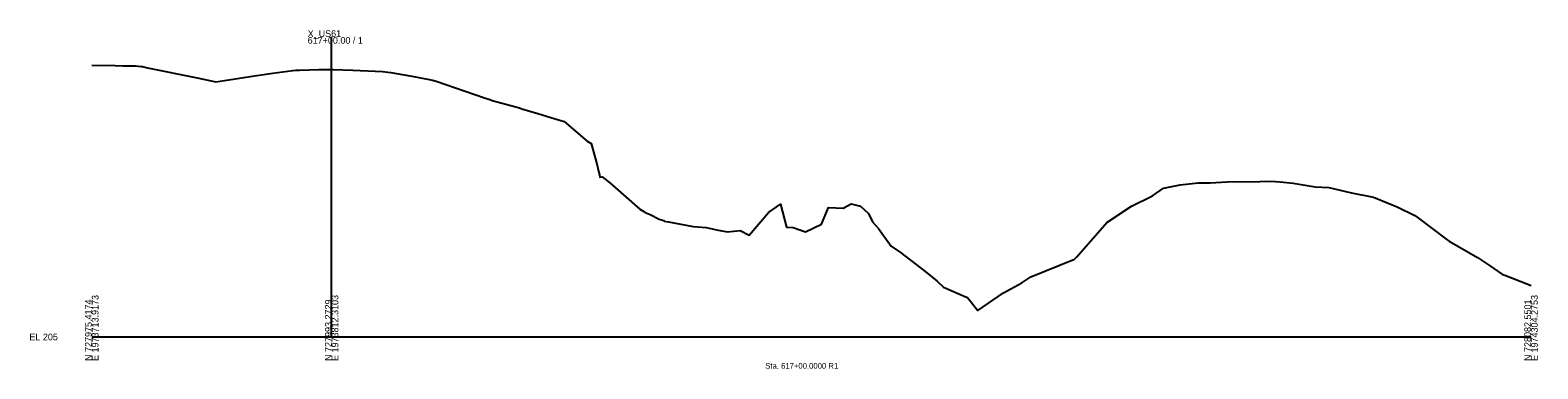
# Model space of a CAD drawing. Extents: x -26 to 1604, y -13 to 9623.
# Drawn here: x 974 to 1603, y 2487 to 2628 of the extents above; entities that cross this region are included whole.
import ezdxf

# ---------------------------------------------------------------- set-up
doc = ezdxf.new("R2010")
doc.units = 0
for name, color, linetype in [('Draft_XS_Grid', 7, 'Continuous'), ('Draft_XS_Text', 7, 'Continuous'), ('DTM_X_GROUND', 7, 'Continuous'), ('XS_CELL', 7, 'Continuous')]:
    doc.layers.add(name, color=color, linetype=linetype)

msp = doc.modelspace()

# ---------------------------------------------------------------- linework, layer by layer
at = {"layer": 'DTM_X_GROUND'}
msp.add_lwpolyline([(1000, 2613.3), (1009.7, 2613.09), (1012.95, 2613.02), (1018.24, 2612.91), (1020.77, 2612.73), (1020.83, 2612.73), (1021.09, 2612.66), (1023.27, 2612.11), (1043.99, 2607.92), (1051.71, 2606.3), (1055.34, 2606.87), (1067.82, 2608.83), (1075.44, 2609.96), (1077.62, 2610.25), (1083.78, 2611.07), (1085.11, 2611.15), (1086.6, 2611.24), (1094.61, 2611.39), (1100.62, 2611.51), (1108.76, 2611.15), (1121.14, 2610.61), (1123.39, 2610.38), (1124.73, 2610.25), (1134.91, 2608.37), (1142.04, 2607.04), (1143.53, 2606.57), (1163.71, 2599.61), (1165.91, 2598.94), (1166.88, 2598.47), (1176.16, 2596.01), (1178.26, 2595.5), (1179.32, 2595.03), (1185.89, 2593.09), (1193.15, 2590.84), (1196.89, 2589.73), (1206.47, 2581.64), (1208.13, 2580.62), (1210.55, 2572.2), (1211.2, 2569.14), (1211.67, 2567.57), (1211.81, 2566.52), (1212.78, 2566.67), (1215.92, 2564.28), (1228.53, 2553.27), (1230.14, 2552.32), (1230.71, 2551.92), (1232.73, 2551.06), (1236.49, 2549.06), (1238.45, 2548.47), (1238.63, 2548.2), (1240.49, 2548.04), (1250.76, 2546), (1256.18, 2545.64), (1261.17, 2544.47), (1265.06, 2543.82), (1270.29, 2544.32), (1274.08, 2542.42), (1282.14, 2551.92), (1287.14, 2555.27), (1289.64, 2545.81), (1292.44, 2545.6), (1297.55, 2543.76), (1304.22, 2546.94), (1307.09, 2553.91), (1307.1, 2553.92), (1307.12, 2553.92), (1313.24, 2553.67), (1316.54, 2555.52), (1320.52, 2554.46), (1323.81, 2551.44), (1325.42, 2548.04), (1328.02, 2545.19), (1333.26, 2537.81), (1337.18, 2535.2), (1347.33, 2527.44), (1352.44, 2523.25), (1355.11, 2520.77), (1364.72, 2516.64), (1365.08, 2516.41), (1369.32, 2511.07), (1380.09, 2518.36), (1387.71, 2522.49), (1391.53, 2525.08), (1409.05, 2532.1), (1409.49, 2532.33), (1410.63, 2533.39), (1423.09, 2547.73), (1433.46, 2554.55), (1442.2, 2558.8), (1446.8, 2562.05), (1453.68, 2563.45), (1461.28, 2564.24), (1466.28, 2564.17), (1473.33, 2564.66), (1487, 2564.76), (1491.54, 2564.89), (1495.47, 2564.62), (1500.79, 2564.07), (1509.96, 2562.56), (1515.74, 2562.27), (1525.12, 2560.09), (1534.34, 2558.26), (1542.86, 2554.82), (1544.18, 2554.26), (1551.61, 2550.57), (1552.58, 2549.89), (1565.04, 2540.41), (1565.83, 2539.85), (1577.73, 2533.06), (1582.66, 2529.74), (1588.12, 2526.08), (1589.06, 2525.75), (1595.49, 2523.2), (1600, 2521.47)], dxfattribs=at)
at = {"layer": 'XS_CELL'}
for p, q in [((1100, 2500), (1100, 2625)), ((1000, 2500), (1100, 2500)), ((1100, 2500), (1600, 2500))]:
    msp.add_line(p, q, dxfattribs=at)

# ---------------------------------------------------------------- texts
at = {"layer": 'Draft_XS_Grid'}
msp.add_text('-', height=0.0001, dxfattribs=at).set_placement((1000, 2500))
at = {"layer": 'Draft_XS_Text'}
msp.add_text('Sta. 617+00.0000 R1', height=2.4, dxfattribs=at).set_placement((1280.75, 2486.75))
at = {"layer": 'XS_CELL'}
for s, p in [('X_US61', (1090, 2625)), ('617+00.00 / 1', (1090, 2622.2)), ('EL 205', (974, 2498.6))]:
    msp.add_text(s, height=2.8, dxfattribs=at).set_placement(p)
for s, p in [('N 727975.4174', (1000, 2490)), ('E 1973713.9173', (1002.8, 2490)), ('N 727993.2729', (1100, 2490)), ('E 1973812.3103', (1102.8, 2490)), ('N 728082.5501', (1600, 2490)), ('E 1974304.2753', (1602.8, 2490))]:
    msp.add_text(s, height=2.8, rotation=90, dxfattribs=at).set_placement(p)

doc.saveas('drawing.dxf')
